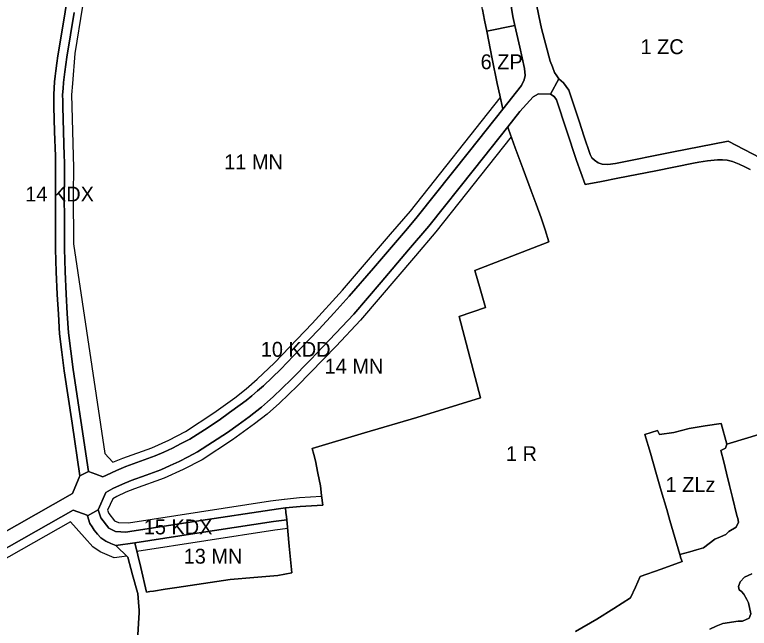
# Model space of a CAD drawing. Extents: x 7423432 to 7425824, y 5537848 to 5539677.
# Drawn here: x 7424610 to 7425103.3, y 5538206.4 to 5538618.6 of the extents above; entities that cross this region are included whole.
import ezdxf

# ---------------------------------------------------------------- set-up
doc = ezdxf.new("R2010")
doc.units = 0
for name, color, linetype in [('linie_rozgraniczajace', 7, 'Continuous'), ('linie_zabudowy_nieprzekraczalne', 7, 'Continuous'), ('oznaczenia_przeznaczen', 7, 'Continuous')]:
    doc.layers.add(name, color=color, linetype=linetype)

msp = doc.modelspace()

# ---------------------------------------------------------------- linework, layer by layer
at = {"layer": 'linie_rozgraniczajace'}
for points in [[(7424915.56, 5538680.19), (7424933.88, 5538681.99), (7424935.26, 5538674.57), (7424935.82, 5538671.58), (7424936.91, 5538665.44), (7424940.68, 5538641.41), (7424944.46, 5538617.37), (7424945.88, 5538611.34), (7424926.95, 5538607.53), (7424925.52, 5538614.86), (7424924.09, 5538622.18), (7424921.89, 5538634.62), (7424919.7, 5538647.06), (7424918.31, 5538657.93), (7424916.91, 5538668.79)], [(7424926.95, 5538607.53), (7424945.88, 5538611.34), (7424949.11, 5538596.87), (7424952.34, 5538582.39), (7424952.69, 5538577.8), (7424952.19, 5538574.92), (7424950.28, 5538571.06), (7424937.7, 5538555.18), (7424935.7, 5538564.65), (7424934.05, 5538572.48), (7424930.71, 5538589)], [(7424665.97, 5538285.93), (7424671.14, 5538297.75), (7424676, 5538300.33), (7424682.3, 5538303.26), (7424688.3, 5538305.73), (7424698.24, 5538309.32), (7424708.18, 5538312.92), (7424714.3, 5538315.68), (7424720.41, 5538318.44), (7424726.58, 5538321.66), (7424732.75, 5538324.88), (7424742.8, 5538331.38), (7424752.85, 5538337.88), (7424760.13, 5538343.19), (7424767.42, 5538348.49), (7424775.62, 5538354.91), (7424779.67, 5538358.46), (7424783.66, 5538361.96), (7424789.71, 5538367.75), (7424795.71, 5538373.49), (7424808.59, 5538386.83), (7424821.46, 5538400.17), (7424829.63, 5538408.82), (7424837.8, 5538417.47), (7424856.14, 5538439.01), (7424874.49, 5538460.55), (7424888.15, 5538476.55), (7424918.67, 5538515.07), (7424941.06, 5538543.32), (7424941.62, 5538541.7), (7424943.82, 5538535.4), (7424946.01, 5538529.1), (7424951.4, 5538514.73), (7424956.78, 5538500.36), (7424960.19, 5538491.25), (7424963.6, 5538482.13), (7424966.14, 5538474.12), (7424968.69, 5538466.11), (7424943.83, 5538456.46), (7424918.98, 5538446.82), (7424922.61, 5538434.36), (7424926.24, 5538421.9), (7424908.4, 5538415.88), (7424922.72, 5538361.33), (7424880.05, 5538348.04), (7424844.95, 5538337.63), (7424809.85, 5538327.23), (7424810.93, 5538323.07), (7424812.02, 5538318.91), (7424813.64, 5538310.55), (7424815.26, 5538302.2), (7424816.04, 5538295.7), (7424816.82, 5538289.2), (7424809.4, 5538288.75), (7424801.75, 5538288.27), (7424791.77, 5538287.29), (7424787.23, 5538286.7), (7424782.7, 5538286.11), (7424735.01, 5538278.73), (7424687.32, 5538271.36), (7424684.66, 5538271.11), (7424681.2, 5538271.32), (7424677.74, 5538271.54), (7424673.24, 5538273.79), (7424667.76, 5538280.73)], [(7425033.23, 5538336.51), (7425041.61, 5538339.26), (7425042.89, 5538336.69), (7425052.64, 5538337.9), (7425062.87, 5538340.74), (7425073.61, 5538342.33), (7425084.34, 5538343.93), (7425088.25, 5538330.18), (7425087.19, 5538327.33), (7425084.25, 5538325.85), (7425086.06, 5538318.22), (7425087.87, 5538310.58), (7425089.91, 5538302.39), (7425091.96, 5538294.19), (7425094.98, 5538282.12), (7425095.46, 5538280.18), (7425096.05, 5538277.8), (7425094.34, 5538274.37), (7425089.46, 5538271.35), (7425087.53, 5538269.49), (7425083.87, 5538267.89), (7425080.21, 5538266.29), (7425076.35, 5538263.43), (7425072.48, 5538260.57), (7425067.86, 5538259.14), (7425063.23, 5538257.71), (7425056.6, 5538255.97), (7425054.4, 5538263.56), (7425052.2, 5538271.15), (7425050.01, 5538278.73), (7425047.81, 5538286.32), (7425044.17, 5538298.87), (7425040.52, 5538311.41), (7425036.88, 5538323.96)], [(7424658.79, 5538281.86), (7424662.38, 5538283.89), (7424665.97, 5538285.93), (7424667.76, 5538280.73), (7424673.24, 5538273.79), (7424677.74, 5538271.54), (7424681.2, 5538271.32), (7424684.66, 5538271.11), (7424687.32, 5538271.36), (7424735.01, 5538278.73), (7424782.7, 5538286.11), (7424787.23, 5538286.7), (7424791.77, 5538287.29), (7424792.12, 5538284.29), (7424792.48, 5538281.29), (7424792.75, 5538279.35), (7424783.83, 5538278.19), (7424730.89, 5538270.08), (7424690.66, 5538263.92), (7424677.96, 5538261.97), (7424674.62, 5538263.43), (7424671.29, 5538264.88), (7424667.83, 5538267.2), (7424665.6, 5538269.73), (7424663.38, 5538272.25), (7424661.97, 5538274.5), (7424660.55, 5538276.76)], [(7424690.66, 5538263.92), (7424730.89, 5538270.08), (7424783.83, 5538278.19), (7424792.75, 5538279.35), (7424794.39, 5538261.56), (7424796.02, 5538243.77), (7424791.39, 5538242.87), (7424786.75, 5538241.97), (7424770.66, 5538240.55), (7424754.58, 5538239.14), (7424745.67, 5538237.81), (7424736.76, 5538236.47), (7424727.86, 5538235.15), (7424718.95, 5538233.82), (7424711.03, 5538232.64), (7424703.11, 5538231.45), (7424700.81, 5538231.11), (7424698.52, 5538230.77), (7424694.59, 5538247.34)]]:
    msp.add_lwpolyline(points, close=True, dxfattribs=at)
for points in [[(7424586.75, 5538261.84), (7424648.72, 5538296.91), (7424653.81, 5538308.93), (7424659.58, 5538311.64), (7424664.43, 5538309.86), (7424669.28, 5538308.08), (7424671.54, 5538309.29), (7424674.92, 5538310.85), (7424678.29, 5538312.42), (7424681.49, 5538313.74), (7424684.69, 5538315.05), (7424694.56, 5538318.62), (7424704.42, 5538322.19), (7424710.23, 5538324.81), (7424716.03, 5538327.44), (7424721.87, 5538330.48), (7424727.71, 5538333.53), (7424737.45, 5538339.83), (7424747.19, 5538346.13), (7424754.29, 5538351.3), (7424761.39, 5538356.47), (7424765.32, 5538359.54), (7424769.24, 5538362.61), (7424773.1, 5538366), (7424776.96, 5538369.39), (7424782.81, 5538374.98), (7424788.65, 5538380.58), (7424801.44, 5538393.83), (7424814.23, 5538407.08), (7424824.45, 5538418.36), (7424834.66, 5538429.63), (7424850.83, 5538448.41), (7424867, 5538467.18), (7424873.66, 5538474.97), (7424880.32, 5538482.76), (7424915.3, 5538526.91), (7424937.7, 5538555.18), (7424950.28, 5538571.06), (7424952.19, 5538574.92), (7424952.69, 5538577.8), (7424952.34, 5538582.39), (7424949.11, 5538596.87), (7424945.88, 5538611.34), (7424944.46, 5538617.37), (7424940.68, 5538641.41)], [(7424646.37, 5538635.99), (7424642.67, 5538613.52), (7424638.97, 5538591.05), (7424638.31, 5538585.97), (7424637.66, 5538580.89), (7424637.23, 5538577.22), (7424636.81, 5538573.56), (7424636.5, 5538569.31), (7424636.19, 5538565.06), (7424636.22, 5538560.87), (7424636.26, 5538556.67), (7424636.78, 5538540.07), (7424637.3, 5538523.47), (7424637.37, 5538519.69), (7424637.44, 5538515.92), (7424637.37, 5538507.04), (7424637.3, 5538498.15), (7424637.34, 5538479.64), (7424637.38, 5538461.13), (7424637.94, 5538445.85), (7424638.5, 5538430.58), (7424639.31, 5538417.43), (7424640.11, 5538404.29), (7424641.69, 5538391.88), (7424643.27, 5538379.47), (7424648.54, 5538344.2), (7424653.81, 5538308.93), (7424648.72, 5538296.91), (7424586.75, 5538261.84)], [(7424649.88, 5538620.13), (7424647.39, 5538605.16), (7424644.91, 5538590.18), (7424644.26, 5538585.17), (7424643.61, 5538580.16), (7424643.2, 5538576.58), (7424642.78, 5538572.99), (7424642.49, 5538568.93), (7424642.19, 5538564.87), (7424642.22, 5538560.8), (7424642.26, 5538556.72), (7424642.78, 5538540.21), (7424643.3, 5538523.7), (7424643.37, 5538519.83), (7424643.44, 5538515.95), (7424643.37, 5538507.04), (7424643.3, 5538498.13), (7424643.34, 5538479.69), (7424643.38, 5538461.25), (7424643.94, 5538446.06), (7424644.5, 5538430.87), (7424645.29, 5538417.86), (7424646.08, 5538404.85), (7424647.65, 5538392.57), (7424649.21, 5538380.29), (7424654.4, 5538345.97), (7424659.58, 5538311.64), (7424653.81, 5538308.93), (7424648.54, 5538344.2), (7424643.27, 5538379.47), (7424641.69, 5538391.88), (7424640.11, 5538404.29), (7424639.31, 5538417.43), (7424638.5, 5538430.58), (7424637.94, 5538445.85), (7424637.38, 5538461.13), (7424637.34, 5538479.64), (7424637.3, 5538498.15), (7424637.37, 5538507.04), (7424637.44, 5538515.92), (7424637.37, 5538519.69), (7424637.3, 5538523.47), (7424636.78, 5538540.07), (7424636.26, 5538556.67), (7424636.22, 5538560.87), (7424636.19, 5538565.06), (7424636.5, 5538569.31), (7424636.81, 5538573.56), (7424637.23, 5538577.22), (7424637.66, 5538580.89), (7424638.31, 5538585.97), (7424638.97, 5538591.05), (7424642.67, 5538613.52), (7424646.37, 5538635.99)], [(7424960.26, 5538626.6), (7424961.98, 5538617.94), (7424963.7, 5538609.29), (7424966.63, 5538598.36), (7424969.57, 5538587.43), (7424971.01, 5538583.57), (7424972.45, 5538579.71), (7424973.95, 5538577.62), (7424975.46, 5538575.53), (7424969.77, 5538565.31), (7424961.65, 5538565.33), (7424958.21, 5538563.33), (7424949.19, 5538553.58), (7424941.06, 5538543.32), (7424918.67, 5538515.07), (7424888.15, 5538476.55), (7424874.49, 5538460.55), (7424856.14, 5538439.01), (7424837.8, 5538417.47), (7424829.63, 5538408.82), (7424821.46, 5538400.17), (7424808.59, 5538386.83), (7424795.71, 5538373.49)], [(7425110.49, 5538522.35), (7425089.18, 5538533.67), (7425051.28, 5538526.16), (7425013.37, 5538518.65), (7425008.36, 5538518.04), (7425004.49, 5538518.28), (7425001.84, 5538519.01), (7424999.36, 5538520.78), (7424997.63, 5538522.46), (7424996.38, 5538524.75), (7424992.25, 5538537.21), (7424989.23, 5538546.34), (7424982.08, 5538567.93), (7424978.57, 5538572.79), (7424975.46, 5538575.53), (7424973.95, 5538577.62), (7424972.45, 5538579.71), (7424971.01, 5538583.57), (7424969.57, 5538587.43), (7424966.63, 5538598.36), (7424963.7, 5538609.29), (7424961.98, 5538617.94), (7424960.26, 5538626.6)], [(7424644.5, 5538430.87), (7424643.94, 5538446.06), (7424643.38, 5538461.25), (7424643.34, 5538479.69), (7424643.3, 5538498.13), (7424643.37, 5538507.04), (7424643.44, 5538515.95), (7424643.37, 5538519.83), (7424643.3, 5538523.7), (7424642.78, 5538540.21), (7424642.26, 5538556.72), (7424642.22, 5538560.8), (7424642.19, 5538564.87), (7424642.49, 5538568.93), (7424642.78, 5538572.99), (7424643.2, 5538576.58), (7424643.61, 5538580.16), (7424644.26, 5538585.17), (7424644.91, 5538590.18), (7424647.39, 5538605.16), (7424649.88, 5538620.13)], [(7424924.09, 5538622.18), (7424925.52, 5538614.86), (7424926.95, 5538607.53), (7424930.71, 5538589), (7424934.05, 5538572.48), (7424935.7, 5538564.65), (7424937.7, 5538555.18), (7424915.3, 5538526.91), (7424880.32, 5538482.76), (7424873.66, 5538474.97), (7424867, 5538467.18), (7424850.83, 5538448.41), (7424834.66, 5538429.63), (7424824.45, 5538418.36), (7424814.23, 5538407.08), (7424801.44, 5538393.83), (7424788.65, 5538380.58), (7424782.81, 5538374.98), (7424776.96, 5538369.39), (7424773.1, 5538366), (7424769.24, 5538362.61), (7424765.32, 5538359.54), (7424761.39, 5538356.47), (7424754.29, 5538351.3), (7424747.19, 5538346.13), (7424737.45, 5538339.83), (7424727.71, 5538333.53), (7424721.87, 5538330.48), (7424716.03, 5538327.44), (7424710.23, 5538324.81), (7424704.42, 5538322.19), (7424694.56, 5538318.62), (7424684.69, 5538315.05), (7424681.49, 5538313.74), (7424678.29, 5538312.42)], [(7424969.77, 5538565.31), (7424975.46, 5538575.53), (7424978.57, 5538572.79), (7424982.08, 5538567.93), (7424989.23, 5538546.34), (7424992.25, 5538537.21), (7424996.38, 5538524.75), (7424997.63, 5538522.46), (7424999.36, 5538520.78), (7425001.84, 5538519.01), (7425004.49, 5538518.28), (7425008.36, 5538518.04), (7425013.37, 5538518.65), (7425051.28, 5538526.16), (7425089.18, 5538533.67), (7425110.49, 5538522.35)], [(7424677.96, 5538261.97), (7424690.66, 5538263.92), (7424694.59, 5538247.34), (7424698.52, 5538230.77), (7424700.81, 5538231.11), (7424703.11, 5538231.45), (7424711.03, 5538232.64), (7424718.95, 5538233.82), (7424727.86, 5538235.15), (7424736.76, 5538236.47), (7424745.67, 5538237.81), (7424754.58, 5538239.14), (7424770.66, 5538240.55), (7424786.75, 5538241.97), (7424791.39, 5538242.87), (7424796.02, 5538243.77), (7424794.39, 5538261.56), (7424792.75, 5538279.35), (7424792.48, 5538281.29), (7424792.12, 5538284.29), (7424791.77, 5538287.29), (7424801.75, 5538288.27), (7424809.4, 5538288.75), (7424816.82, 5538289.2), (7424816.04, 5538295.7), (7424815.26, 5538302.2), (7424813.64, 5538310.55), (7424812.02, 5538318.91), (7424810.93, 5538323.07), (7424809.85, 5538327.23), (7424844.95, 5538337.63), (7424880.05, 5538348.04), (7424922.72, 5538361.33), (7424908.4, 5538415.88), (7424926.24, 5538421.9), (7424922.61, 5538434.36), (7424918.98, 5538446.82), (7424943.83, 5538456.46), (7424968.69, 5538466.11), (7424966.14, 5538474.12), (7424963.6, 5538482.13), (7424960.19, 5538491.25), (7424956.78, 5538500.36), (7424951.4, 5538514.73), (7424946.01, 5538529.1), (7424943.82, 5538535.4), (7424941.62, 5538541.7), (7424941.06, 5538543.32), (7424949.19, 5538553.58), (7424958.21, 5538563.33), (7424961.65, 5538565.33), (7424969.77, 5538565.31), (7424972.15, 5538563.57), (7424973.7, 5538561.5), (7424980.44, 5538541.13), (7424987.17, 5538520.75), (7424993.06, 5538504.43), (7425004, 5538506.6), (7425014.94, 5538508.76), (7425040.41, 5538513.81), (7425065.88, 5538518.86), (7425069.42, 5538519.43), (7425075.24, 5538520.34), (7425077.51, 5538520.68), (7425081.89, 5538521.14), (7425085.32, 5538521.19), (7425088.51, 5538520.81), (7425092.01, 5538519.88), (7425096.56, 5538518.1), (7425100.17, 5538516.35), (7425103.78, 5538514.59)], [(7425103.78, 5538514.59), (7425100.17, 5538516.35), (7425096.56, 5538518.1), (7425092.01, 5538519.88), (7425088.51, 5538520.81), (7425085.32, 5538521.19), (7425081.89, 5538521.14), (7425077.51, 5538520.68), (7425075.24, 5538520.34), (7425069.42, 5538519.43), (7425065.88, 5538518.86), (7425040.41, 5538513.81), (7425014.94, 5538508.76), (7425004, 5538506.6), (7424993.06, 5538504.43), (7424987.17, 5538520.75), (7424980.44, 5538541.13), (7424973.7, 5538561.5), (7424972.15, 5538563.57), (7424969.77, 5538565.31)], [(7424678.29, 5538312.42), (7424674.92, 5538310.85), (7424671.54, 5538309.29), (7424669.28, 5538308.08), (7424664.43, 5538309.86), (7424659.58, 5538311.64), (7424654.4, 5538345.97), (7424649.21, 5538380.29), (7424647.65, 5538392.57), (7424646.08, 5538404.85), (7424645.29, 5538417.86), (7424644.5, 5538430.87)], [(7424795.71, 5538373.49), (7424789.71, 5538367.75), (7424783.66, 5538361.96), (7424779.67, 5538358.46), (7424775.62, 5538354.91), (7424767.42, 5538348.49), (7424760.13, 5538343.19), (7424752.85, 5538337.88), (7424742.8, 5538331.38), (7424732.75, 5538324.88), (7424726.58, 5538321.66), (7424720.41, 5538318.44), (7424714.3, 5538315.68), (7424708.18, 5538312.92), (7424698.24, 5538309.32), (7424688.3, 5538305.73), (7424682.3, 5538303.26), (7424676, 5538300.33), (7424671.14, 5538297.75), (7424665.97, 5538285.93), (7424662.38, 5538283.89), (7424658.79, 5538281.86), (7424658.6, 5538282.41), (7424649.28, 5538285.74), (7424589.55, 5538251.94)], [(7425116.26, 5538338.55), (7425102.26, 5538334.37), (7425088.25, 5538330.18), (7425084.34, 5538343.93), (7425073.61, 5538342.33), (7425062.87, 5538340.74), (7425052.64, 5538337.9), (7425042.89, 5538336.69), (7425041.61, 5538339.26)], [(7425041.61, 5538339.26), (7425033.23, 5538336.51), (7425036.88, 5538323.96), (7425040.52, 5538311.41), (7425044.17, 5538298.87), (7425047.81, 5538286.32), (7425050.01, 5538278.73), (7425052.2, 5538271.15), (7425054.4, 5538263.56), (7425056.6, 5538255.97), (7425057.35, 5538253.59), (7425058.1, 5538251.2), (7425044.09, 5538246.17), (7425030.09, 5538241.14), (7425026.84, 5538234.02), (7425023.58, 5538226.91), (7425012.2, 5538219.78), (7425000.82, 5538212.65), (7424986.57, 5538204.28)], [(7424986.57, 5538204.28), (7425000.82, 5538212.65), (7425012.2, 5538219.78), (7425023.58, 5538226.91), (7425026.84, 5538234.02), (7425030.09, 5538241.14), (7425044.09, 5538246.17), (7425058.1, 5538251.2), (7425057.35, 5538253.59), (7425056.6, 5538255.97), (7425063.23, 5538257.71), (7425067.86, 5538259.14), (7425072.48, 5538260.57), (7425076.35, 5538263.43), (7425080.21, 5538266.29), (7425083.87, 5538267.89), (7425087.53, 5538269.49), (7425089.46, 5538271.35), (7425094.34, 5538274.37), (7425096.05, 5538277.8), (7425095.46, 5538280.18), (7425094.98, 5538282.12), (7425091.96, 5538294.19), (7425089.91, 5538302.39), (7425087.87, 5538310.58), (7425086.06, 5538318.22), (7425084.25, 5538325.85), (7425087.19, 5538327.33), (7425088.25, 5538330.18), (7425102.26, 5538334.37), (7425116.26, 5538338.55)], [(7424589.55, 5538251.94), (7424649.28, 5538285.74), (7424658.6, 5538282.41), (7424658.79, 5538281.86), (7424660.55, 5538276.76), (7424661.97, 5538274.5), (7424663.38, 5538272.25), (7424665.6, 5538269.73), (7424667.83, 5538267.2), (7424671.29, 5538264.88), (7424674.62, 5538263.43), (7424677.96, 5538261.97), (7424685.87, 5538254.12), (7424689.12, 5538242.31), (7424692.37, 5538230.5), (7424692.62, 5538229.89), (7424693.14, 5538224.09), (7424693.67, 5538218.29), (7424693.51, 5538217.14), (7424693.12, 5538209.54), (7424692.72, 5538201.94)], [(7424692.72, 5538201.94), (7424693.12, 5538209.54), (7424693.51, 5538217.14), (7424693.67, 5538218.29), (7424693.14, 5538224.09), (7424692.62, 5538229.89), (7424692.37, 5538230.5), (7424689.12, 5538242.31), (7424685.87, 5538254.12), (7424677.96, 5538261.97)], [(7425104.89, 5538243.1), (7425100.15, 5538240.76), (7425097.06, 5538237.58), (7425095.99, 5538234.41), (7425096.52, 5538232.18), (7425097.95, 5538231.19), (7425099.57, 5538229.41), (7425101.71, 5538225.86), (7425102.8, 5538223.48), (7425104.19, 5538216.25), (7425103.12, 5538213.21), (7425098.61, 5538211.31), (7425095.78, 5538211.13), (7425085.5, 5538209.7), (7425081.1, 5538207.82), (7425076.69, 5538205.94)], [(7425076.69, 5538205.94), (7425081.1, 5538207.82), (7425085.5, 5538209.7), (7425095.78, 5538211.13), (7425098.61, 5538211.31), (7425103.12, 5538213.21), (7425104.19, 5538216.25), (7425102.8, 5538223.48), (7425101.71, 5538225.86), (7425099.57, 5538229.41), (7425097.95, 5538231.19), (7425096.52, 5538232.18), (7425095.99, 5538234.41), (7425097.06, 5538237.58), (7425100.15, 5538240.76), (7425104.89, 5538243.1)]]:
    msp.add_lwpolyline(points, dxfattribs=at)
at = {"layer": 'linie_zabudowy_nieprzekraczalne'}
for points in [[(7424655.62, 5538624.25), (7424650.44, 5538592.49), (7424650.44, 5538592.49), (7424648.76, 5538572.43), (7424648.19, 5538564.68), (7424648.26, 5538556.84), (7424649.3, 5538523.86), (7424649.44, 5538515.99), (7424649.3, 5538498.12), (7424649.38, 5538464.57), (7424670.54, 5538323.92), (7424675.88, 5538317.92), (7424682.53, 5538320.65), (7424702.16, 5538327.75), (7424713.41, 5538332.83), (7424724.69, 5538338.72), (7424743.79, 5538351.08), (7424757.78, 5538361.26), (7424765.41, 5538367.23), (7424772.9, 5538373.81), (7424784.42, 5538384.83), (7424809.85, 5538411.18), (7424830.17, 5538433.61), (7424862.45, 5538471.09), (7424875.68, 5538486.57), (7424936.09, 5538562.81)], [(7424943.4, 5538536.6), (7424892.79, 5538472.74), (7424879.05, 5538456.66), (7424842.27, 5538413.46), (7424825.8, 5538396.03), (7424799.94, 5538369.24), (7424787.77, 5538357.59), (7424779.45, 5538350.28), (7424771.03, 5538343.7), (7424756.25, 5538332.94), (7424735.78, 5538319.69), (7424723.03, 5538313.04), (7424710.44, 5538307.36), (7424690.46, 5538300.13), (7424684.71, 5538297.76), (7424678.67, 5538294.96), (7424675.8, 5538293.43), (7424672.4, 5538285.67), (7424673.1, 5538283.65), (7424677.12, 5538278.55), (7424679.71, 5538277.47), (7424686.4, 5538277.29), (7424781.85, 5538292.05), (7424791.01, 5538293.24), (7424791.17, 5538293.26), (7424801.27, 5538294.25), (7424816.1, 5538295.17)], [(7424685.21, 5538254.77), (7424676.74, 5538253.77), (7424667.43, 5538257.84), (7424662.51, 5538261.14), (7424656.95, 5538267.45), (7424656.95, 5538267.45), (7424656.95, 5538267.45), (7424647.55, 5538277.87), (7424532.93, 5538213)], [(7424793.3, 5538273.37), (7424784.67, 5538272.25), (7424692.08, 5538257.93)]]:
    msp.add_lwpolyline(points, dxfattribs=at)

# ---------------------------------------------------------------- texts
at = {"layer": 'oznaczenia_przeznaczen'}
for s, p in [('1 ZC', (7425030.24, 5538592.1)), ('6 ZP', (7424922.86, 5538581.96)), ('11 MN', (7424750.69, 5538514.75)), ('14 KDX', (7424617.12, 5538493.13)), ('10 KDD', (7424775.26, 5538388.83)), ('14 MN', (7424818.11, 5538377.47)), ('1 R', (7424939.88, 5538318.76)), ('1 ZLz', (7425047.05, 5538297.99)), ('15 KDX', (7424696.69, 5538269.52)), ('13 MN', (7424723.48, 5538249.85))]:
    msp.add_text(s, height=10, dxfattribs=at).set_placement(p)

doc.saveas('drawing.dxf')
